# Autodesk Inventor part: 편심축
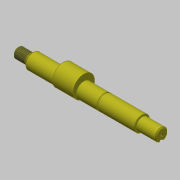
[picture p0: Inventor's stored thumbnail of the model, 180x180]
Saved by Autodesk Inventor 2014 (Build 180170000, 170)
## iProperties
Created: 2016-08
Part Number: 편심축
Material: 강철, 탄소
Document SubType Name: Modeling
Designer: mduedu
Density: 7.87 g/cm^3
Appearance: Canary
Author: mduedu
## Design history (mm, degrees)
sketch "스케치1"
  geometry: L1 (-70, 0)-(70, 0); L2 (-70, 0)-(-70, 5); L3 (-70, 5)-(-56, 5); L4 (-56, 5)-(-56, 7.5); L5 (-56, 7.5)-(51, 7.5); L6 (51, 7.5)-(51, 6); L7 (51, 6)-(70, 6); L8 (70, 6)-(70, 0); 2 further points
  constraints: 16 end point, 5 parallel, 2 perpendicular, 1 coincident, 1 horizontal, 1 midpoint
  dimensions: "d0" = 140 distance of L1.start L1.end; "d2" = 14 distance of L2.end L3.end; "d3" = 19 distance of L6.end L7.end; "d4" = 10 diameter of L3 L1; "d5" = 15 diameter of L5 L1; "d6" = 12 diameter of L7 L1
revolve "회전1" sketch "스케치1" stored, may be unused: angle "d7" = 90 deg
sketch "스케치2"
  geometry: L1 (-56, -5)-(-56, 5) reference; L2 (70, -6)-(70, 6) reference; L3 (-56, 0)-(70, 0); L4 (-58, 4.5)-(-58, 5); L5 (-58, 5)-(-56, 5); L6 (-56, 5)-(-56, 4.5); L7 (-58, 4.5)-(-56, 4.5); 1 further point
  constraints: 10 end point, 2 midpoint, 1 parallel, 1 perpendicular, 1 point on line
  dimensions: "d8" = 2 distance of L4.end L5.end; "d10" = 10 diameter of L5 L3; "d11" = 9 diameter of L7 L3
revolve "회전2" sketch "스케치2" stored, may be unused: angle "d12" = 90 deg
node "작업 평면1"
sketch "스케치3"
  geometry: C1 r 10.5 at (0, 3); C2 r 7.5 at (0, 0) reference; 1 further point
  constraints: 1 centre point, 1 tangent, 1 vertical alignment
  dimensions: "d14" = 3 distance of C1.centre point (0, 0); "d15" = 21 diameter of C1 (derived)
extrude "돌출1" join sketch "스케치3" distance "d16" = 20; taper "d17" = 0 deg
sketch "스케치5"
  geometry: L1 (-70, -5)-(-70, 5) reference; L2 (70, -6)-(70, 6) reference; L3 (-70, 0)-(70, 0); L4 (-6, 7.5)-(51, 7.5) reference; L5 (15.15, 7.5)-(14, 7.5); L6 (14, 7.5)-(14, 7.15); L7 (14, 7.15)-(15.15, 7.15); L8 (15.15, 7.15)-(15.15, 7.5); 1 further point
  constraints: 10 end point, 2 midpoint, 2 parallel, 1 horizontal, 1 perpendicular, 1 point on line
  dimensions: "d19" = 56 distance between parallel lines of L6 L2; "d20" = 1.15 distance between parallel lines of L8 L6; "d21" = 14.3 diameter of L7 L3
revolve "회전3" sketch "스케치5" stored, may be unused: angle "d22" = 90 deg
node "작업 평면3"
sketch "스케치6"
  geometry: L1 (9.5, 7.5)-(9.5, -7.5) reference; L2 (7.5, 2)-(-9.5, 2); L3 (-9.5, 2)-(-9.5, -2); L4 (-9.5, -2)-(7.5, -2); L5 (-9.5, 6)-(-9.5, -6) reference; A1 r 2 centre (7.5, 0) between (7.5, -2) and (7.5, 2); 2 further points
  constraints: 6 end point, 3 tangent, 2 midpoint, 2 point on circle, 1 centre point, 1 horizontal, 1 horizontal alignment, 1 parallel, 1 perpendicular
  dimensions: "d23" = 4 distance between parallel lines of L4 L2
extrude "돌출2" cut sketch "스케치6" distance "d25" = 2.5; taper "d26" = 0 deg
feature "스레드1" dims "d27" = 10, "d28" = 0
chamfer "모따기5" distance "d41" = 0.5; stored, may be unused: second distance "d42" = 2, angle "d43" = 45 deg
chamfer "모따기6" distance "d44" = 0.5; stored, may be unused: second distance "d45" = 2, angle "d46" = 45 deg
chamfer "모따기7" distance "d47" = 1; stored, may be unused: second distance "d48" = 2, angle "d49" = 45 deg
chamfer "모따기8" distance "d50" = 1; stored, may be unused: second distance "d51" = 2, angle "d52" = 45 deg
sketch "스케치8"
  geometry: 1 further point
hole "구멍1" sketch "스케치8" at (2, 3.5) diameter "d53" = 3.242; stored, may be unused: countersink angle "d57" = 90 deg, drill point angle "d59" = 120 deg; dims "d54" = 10, "d55" = 4, "d56" = 2, "d58" = 12
node "솔리드1"
other parameters: "d13" = -44
